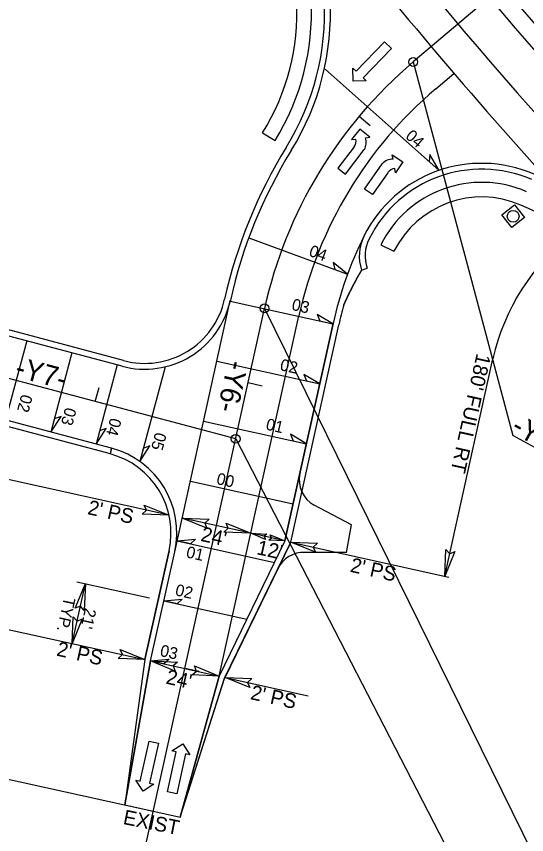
# Model space of a CAD drawing. Extents: x 1762196 to 1766326, y 709922 to 713142.
# Drawn here: x 1763983.5 to 1764158, y 711023.4 to 711303.2 of the extents above; entities that cross this region are included whole.
import ezdxf

# ---------------------------------------------------------------- set-up
doc = ezdxf.new("R2010")
doc.units = 0
for name, color, linetype in [('Default', 7, 'Continuous'), ('Old_Level_3', 7, 'Continuous'), ('Pattern 1', 7, 'Continuous'), ('Pattern 2', 7, 'Continuous'), ('Prop Conc 2ft 6in Curb and Gutter', 7, 'Continuous'), ('Prop Dimension', 7, 'Continuous'), ('Prop EOT', 7, 'Continuous'), ('Prop Horizontal Alignment', 7, 'Continuous'), ('Prop Horizontal Alignment Direction Label', 7, 'Continuous'), ('Prop Horizontal Alignment Station Label', 7, 'Continuous'), ('Prop Horizontal Alignment Tick Small', 7, 'Continuous'), ('Prop Lane Arrow CELL', 7, 'Continuous'), ('Prop Lane Lines', 7, 'Continuous'), ('Prop Paved Shoulder', 7, 'Continuous'), ('Prop Shade Medium', 7, 'Continuous'), ('Prop Superelevation  Arrow CELL', 7, 'Continuous'), ('Prop Superelevation Label', 7, 'Continuous'), ('Prop Terminator CELL', 7, 'Continuous')]:
    doc.layers.add(name, color=color, linetype=linetype)

msp = doc.modelspace()

# ---------------------------------------------------------------- linework, layer by layer
at = {"layer": 'Default'}
msp.add_lwpolyline([(1764157.32, 711234.37), (1764152.96, 711230.97), (1764149.56, 711235.32), (1764153.92, 711238.73)], close=True, dxfattribs=at)
msp.add_circle((1764153.42, 711234.8), 2.03, dxfattribs=at)
at = {"layer": 'Old_Level_3'}
for p, q in [((1764098.14, 711129.25), (1764085.4, 711135.99)), ((1764096.46, 711119.8), (1764098.14, 711129.25)), ((1764096.46, 711119.8), (1764082.2, 711119.9))]:
    msp.add_line(p, q, dxfattribs=at)
for centre, start, end in [((1764090.25, 711144.74), 167.5238, 241.0076), ((1764081.9, 711109.9), 88.294, 154.0891)]:
    msp.add_arc(centre, 10, start, end, dxfattribs=at)
at = {"layer": 'Pattern 1'}
for p, q in [((1764067.74, 711263.33), (1764071.99, 711260.71)), ((1764108.18, 711225.07), (1764112.66, 711222.84))]:
    msp.add_line(p, q, dxfattribs=at)
for centre, radius, start, end in [((1764000.95, 711304.58), 83.5, 328.2999, 36.9925), ((1764000.95, 711304.58), 78.5, 328.2999, 36.9925), ((1764142.65, 711207.92), 38.5, 66.4571, 153.5523), ((1764142.65, 711207.92), 33.5, 66.4571, 153.5523), ((1764088.73, 711084.16), 168.5, 44.7299, 66.4571)]:
    msp.add_arc(centre, radius, start, end, dxfattribs=at)
at = {"layer": 'Pattern 2'}
for p, q in [((1764067.74, 711263.33), (1764071.99, 711260.71)), ((1764108.18, 711225.07), (1764112.66, 711222.84))]:
    msp.add_line(p, q, dxfattribs=at)
for centre, radius, start, end in [((1764000.95, 711304.58), 83.5, 328.2999, 36.9925), ((1764000.95, 711304.58), 78.5, 328.2999, 36.9925), ((1764142.65, 711207.92), 38.5, 66.4571, 153.5523), ((1764142.65, 711207.92), 33.5, 66.4571, 153.5523), ((1764088.73, 711084.16), 168.5, 44.7299, 66.4571)]:
    msp.add_arc(centre, radius, start, end, dxfattribs=at)
at = {"layer": 'Prop Conc 2ft 6in Curb and Gutter'}
for p, q in [((1764101.6, 711216.43), (1764103.49, 711217.08)), ((1764020.2, 711185.46), (1763932.48, 711208.83)), ((1764015.67, 711153.55), (1763924.24, 711177.91)), ((1764015.67, 711153.55), (1764016.1, 711155.51))]:
    msp.add_line(p, q, dxfattribs=at)
for centre, radius, start, end in [((1764000.95, 711304.58), 88, 328.2999, 36.9925), ((1764218.76, 711170.06), 168, 148.2999, 167.4899), ((1764142.65, 711207.92), 43, 66.4571, 153.5523), ((1764115.79, 711221.28), 13, 153.5523, 198.869), ((1764027.41, 711212.52), 28, 255.0839, 347.4899)]:
    msp.add_arc(centre, radius, start, end, dxfattribs=at)
at = {"layer": 'Prop Dimension'}
for p, q in [((1764130.06, 711111.71), (1764146.5, 711186.05)), ((1764035.72, 711132.59), (1763933.52, 711155.2)), ((1764063.66, 711126.4), (1764040.23, 711131.59)), ((1764075.38, 711123.81), (1764063.66, 711126.4)), ((1764077.33, 711123.38), (1764131.45, 711111.4)), ((1763922.72, 711106.38), (1764027.47, 711083.2)), ((1764029.43, 711082.77), (1764052.86, 711077.58)), ((1764054.87, 711077.14), (1764083.34, 711070.84))]:
    msp.add_line(p, q, dxfattribs=at)
msp.add_arc((1764218.76, 711170.06), 74, 127.3856, 167.5238, dxfattribs=at)
at = {"layer": 'Prop EOT'}
for p, q in [((1764019.69, 711183.53), (1763931.97, 711206.9)), ((1764075.38, 711123.81), (1764091.83, 711198.15)), ((1764016.1, 711155.51), (1763924.76, 711179.84)), ((1764075.38, 711123.81), (1764052.86, 711077.58)), ((1764029.43, 711082.77), (1764037.67, 711120.04)), ((1764029.43, 711082.77), (1764020.61, 711033.51)), ((1764039.58, 711029.31), (1764052.86, 711077.58)), ((1764020.61, 711033.51), (1764039.58, 711029.31))]:
    msp.add_line(p, q, dxfattribs=at)
for centre, radius, start, end in [((1764000.95, 711304.58), 90, 328.2999, 36.9925), ((1764218.76, 711170.06), 166, 148.2999, 167.4899), ((1764142.65, 711207.92), 45, 66.4571, 153.5523), ((1764218.76, 711170.06), 130, 153.5523, 167.5238), ((1764027.41, 711212.52), 30, 255.0839, 347.4899), ((1764008.38, 711126.52), 30, 347.5238, 75.0839)]:
    msp.add_arc(centre, radius, start, end, dxfattribs=at)
at = {"layer": 'Prop Horizontal Alignment'}
for p, q in [((1764149.82, 711313.49), (1764119.23, 711287.58)), ((1763997.94, 710884.9), (1764068.39, 711203.33)), ((1764058.52, 711158.7), (1763913.87, 711197.23))]:
    msp.add_line(p, q, dxfattribs=at)
for centre, radius, start, end in [((1765296.46, 712280.56), 1500, 216.32502, 240.8436), ((1764218.76, 711170.06), 154, 130.2612, 167.5238)]:
    msp.add_arc(centre, radius, start, end, dxfattribs=at)
at = {"layer": 'Prop Horizontal Alignment Station Label'}
for p, q in [((1764119.23, 711287.58), (1764153.33, 711159.89)), ((1764068.39, 711203.33), (1764195.76, 710944.38)), ((1764248.6, 711106.84), (1764153.33, 711159.89)), ((1764058.52, 711158.7), (1764174.11, 710934.74)), ((1763823.81, 711077.05), (1764030.34, 711031.36))]:
    msp.add_line(p, q, dxfattribs=at)
for centre in [(1764119.23, 711287.58), (1764068.39, 711203.33), (1764058.52, 711158.7)]:
    msp.add_circle(centre, 1.5, dxfattribs=at)
at = {"layer": 'Prop Horizontal Alignment Tick Small'}
for p, q in [((1764104.55, 711265.75), (1764100.71, 711268.96)), ((1764010.5, 711171.49), (1764011.78, 711176.32)), ((1764067.63, 711176.73), (1764062.75, 711177.81)), ((1764046.03, 711079.1), (1764041.14, 711080.18))]:
    msp.add_line(p, q, dxfattribs=at)
at = {"layer": 'Prop Lane Arrow CELL'}
for p, q in [((1764099.7, 711284.47), (1764109.46, 711294.51)), ((1764109.46, 711294.51), (1764111.82, 711292.22)), ((1764111.82, 711292.22), (1764102.07, 711282.17)), ((1764098.73, 711281.03), (1764098.63, 711285.52)), ((1764098.63, 711285.52), (1764099.7, 711284.47)), ((1764103.15, 711281.13), (1764098.73, 711281.03)), ((1764102.07, 711282.17), (1764103.15, 711281.13)), ((1764100.95, 711264.58), (1764098.18, 711261.04)), ((1764104.42, 711261.88), (1764100.95, 711264.58)), ((1764098.18, 711261.04), (1764099.65, 711261.23)), ((1764102.94, 711261.68), (1764104.42, 711261.88)), ((1764099.05, 711258.55), (1764093.5, 711251.27)), ((1764096.13, 711249.27), (1764102.52, 711257.66)), ((1764112.34, 711254.39), (1764112.08, 711255.85)), ((1764112.08, 711255.85), (1764115.72, 711253.38)), ((1764102.61, 711244.11), (1764108.65, 711252.76)), ((1764115.72, 711253.38), (1764113.19, 711249.66)), ((1764093.5, 711251.27), (1764096.13, 711249.27)), ((1764110.55, 711249.73), (1764105.32, 711242.22)), ((1764113.19, 711249.66), (1764112.93, 711251.12)), ((1764105.32, 711242.22), (1764102.61, 711244.11)), ((1764025.87, 711041.65), (1764028.9, 711055.32)), ((1764028.9, 711055.32), (1764032.12, 711054.6)), ((1764032.12, 711054.6), (1764029.09, 711040.93)), ((1764036.73, 711052.02), (1764040.43, 711054.42)), ((1764040.43, 711054.42), (1764042.88, 711050.66)), ((1764035.16, 711038.03), (1764038.19, 711051.7)), ((1764038.19, 711051.7), (1764036.73, 711052.02)), ((1764041.41, 711050.98), (1764038.38, 711037.31)), ((1764042.88, 711050.66), (1764041.41, 711050.98)), ((1764026.85, 711038.2), (1764024.4, 711041.97)), ((1764024.4, 711041.97), (1764025.87, 711041.65)), ((1764030.55, 711040.61), (1764026.85, 711038.2)), ((1764029.09, 711040.93), (1764030.55, 711040.61)), ((1764038.38, 711037.31), (1764035.16, 711038.03))]:
    msp.add_line(p, q, dxfattribs=at)
for centre, radius, start, end in [((1764096.46, 711260.53), 3.28, 322.6881, 12.3463), ((1764097.93, 711260.17), 5.25, 331.3642, 16.6759), ((1764112.44, 711249.15), 5.25, 91.1316, 136.4433), ((1764113.23, 711247.87), 3.28, 95.4612, 145.1194)]:
    msp.add_arc(centre, radius, start, end, dxfattribs=at)
at = {"layer": 'Prop Lane Lines'}
for p, q in [((1764126.99, 711278.42), (1764133.18, 711283.67)), ((1764037.67, 711120.04), (1764056.69, 711205.99)), ((1764052.86, 711077.58), (1764080.11, 711200.74))]:
    msp.add_line(p, q, dxfattribs=at)
for centre, radius, start, end in [((1765296.46, 712280.56), 1494, 216.32502, 222.11492), ((1765296.46, 712280.56), 1506, 216.32502, 222.11492), ((1765296.46, 712280.56), 1520, 216.32502, 224.72992), ((1765296.46, 712280.56), 1532, 217.53858, 222.47123), ((1764218.76, 711170.06), 142, 130.2612, 167.5238)]:
    msp.add_arc(centre, radius, start, end, dxfattribs=at)
at = {"layer": 'Prop Paved Shoulder'}
for p, q in [((1764077.33, 711123.38), (1764093.78, 711197.71)), ((1764077.33, 711123.38), (1764054.66, 711076.71)), ((1764027.47, 711083.2), (1764035.72, 711120.47)), ((1764027.47, 711083.2), (1764020.61, 711033.51)), ((1764039.58, 711029.31), (1764054.79, 711077.05))]:
    msp.add_line(p, q, dxfattribs=at)
for centre, radius, start, end in [((1764115.79, 711221.28), 15, 153.5523, 198.869), ((1764218.76, 711170.06), 128, 164.3625, 167.5238), ((1764008.38, 711126.52), 28, 347.5238, 75.0839)]:
    msp.add_arc(centre, radius, start, end, dxfattribs=at)
msp.add_spline([(1764101.6, 711216.43), (1764101.46, 711216.19), (1764101.33, 711215.96), (1764101.19, 711215.73), (1764101.06, 711215.49), (1764100.93, 711215.26), (1764100.79, 711215.03), (1764100.66, 711214.79), (1764100.53, 711214.56), (1764100.4, 711214.32), (1764100.27, 711214.09), (1764100.14, 711213.85), (1764100.01, 711213.62), (1764099.88, 711213.38), (1764099.75, 711213.14), (1764099.62, 711212.91), (1764099.49, 711212.67), (1764099.36, 711212.43), (1764099.24, 711212.19), (1764099.11, 711211.96), (1764098.98, 711211.72), (1764098.86, 711211.48), (1764098.73, 711211.24), (1764098.61, 711211), (1764098.48, 711210.76), (1764098.36, 711210.52), (1764098.23, 711210.28), (1764098.11, 711210.04), (1764097.99, 711209.79), (1764097.87, 711209.55), (1764097.75, 711209.31), (1764097.63, 711209.07), (1764097.5, 711208.83), (1764097.38, 711208.58), (1764097.27, 711208.34), (1764097.15, 711208.09), (1764097.03, 711207.85), (1764096.91, 711207.61), (1764096.79, 711207.36), (1764096.67, 711207.12), (1764096.56, 711206.87), (1764096.44, 711206.62), (1764096.33, 711206.38), (1764096.21, 711206.13), (1764096.1, 711205.89), (1764095.98, 711205.64), (1764095.87, 711205.39), (1764095.76, 711205.14), (1764095.64, 711204.89), (1764095.53, 711204.65), (1764095.49, 711204.56)], degree=3, dxfattribs=at)
at = {"layer": 'Prop Shade Medium'}
for p, q in [((1764101.6, 711216.43), (1764101.6, 711216.43)), ((1764101.6, 711216.43), (1764101.6, 711216.43)), ((1764091.83, 711198.15), (1764075.38, 711123.81)), ((1764077.33, 711123.38), (1764093.78, 711197.71)), ((1764016.1, 711155.51), (1764015.59, 711153.57)), ((1764016.1, 711155.51), (1764015.59, 711153.57)), ((1764075.38, 711123.81), (1764052.86, 711077.58)), ((1764054.72, 711076.83), (1764077.33, 711123.38)), ((1764035.72, 711120.47), (1764027.47, 711083.2)), ((1764029.43, 711082.77), (1764037.67, 711120.04)), ((1764027.47, 711083.2), (1764020.61, 711033.51)), ((1764020.61, 711033.51), (1764029.43, 711082.77)), ((1764052.86, 711077.58), (1764039.58, 711029.31)), ((1764039.58, 711029.31), (1764054.72, 711076.83))]:
    msp.add_line(p, q, dxfattribs=at)
for centre, radius, start, end in [((1764218.76, 711170.06), 130, 153.5523, 167.5238), ((1764115.79, 711221.28), 15, 153.5523, 198.869), ((1764218.76, 711170.06), 128, 164.3625, 167.5238), ((1764008.38, 711126.52), 30, 347.5238, 75.0839), ((1764008.38, 711126.52), 28, 347.5238, 75.0839)]:
    msp.add_arc(centre, radius, start, end, dxfattribs=at)
for points in [[(1764098.39, 711210.58), (1764098.48, 711210.76), (1764098.61, 711211), (1764098.73, 711211.24), (1764098.86, 711211.48), (1764098.98, 711211.72), (1764099.11, 711211.96), (1764099.24, 711212.19), (1764099.36, 711212.43), (1764099.49, 711212.67), (1764099.62, 711212.91), (1764099.75, 711213.14), (1764099.88, 711213.38), (1764100.01, 711213.62), (1764100.14, 711213.85), (1764100.27, 711214.09), (1764100.4, 711214.32), (1764100.53, 711214.56), (1764100.66, 711214.79), (1764100.79, 711215.03), (1764100.93, 711215.26), (1764101.06, 711215.49), (1764101.19, 711215.73), (1764101.33, 711215.96), (1764101.46, 711216.19), (1764101.6, 711216.43)], [(1764095.49, 711204.56), (1764095.53, 711204.65), (1764095.64, 711204.89), (1764095.76, 711205.14), (1764095.87, 711205.39), (1764095.98, 711205.64), (1764096.1, 711205.89), (1764096.21, 711206.13), (1764096.33, 711206.38), (1764096.44, 711206.62), (1764096.56, 711206.87), (1764096.67, 711207.12), (1764096.79, 711207.36), (1764096.91, 711207.61), (1764097.03, 711207.85), (1764097.15, 711208.09), (1764097.27, 711208.34), (1764097.38, 711208.58), (1764097.5, 711208.83), (1764097.63, 711209.07), (1764097.75, 711209.31), (1764097.87, 711209.55), (1764097.99, 711209.79), (1764098.11, 711210.04), (1764098.23, 711210.28), (1764098.36, 711210.52), (1764098.39, 711210.58)]]:
    msp.add_spline(points, degree=3, dxfattribs=at)
at = {"layer": 'Prop Superelevation  Arrow CELL'}
for points in [[(1764128.11, 711250.5), (1764124.95, 711255.98), (1764124.65, 711253.57)], [(1764096.78, 711215.03), (1764091.85, 711218.99), (1764092.44, 711216.63)], [(1764091.8, 711198.02), (1764086.37, 711201.26), (1764087.28, 711199.01)], [(1764087.26, 711177.51), (1764081.83, 711180.76), (1764082.74, 711178.51)], [(1763995.3, 711161.05), (1763998.78, 711166.33), (1763996.49, 711165.52)], [(1764010.76, 711156.93), (1764014.24, 711162.21), (1764011.95, 711161.4)], [(1764082.72, 711157.01), (1764077.3, 711160.26), (1764078.21, 711158.01)], [(1764025.73, 711150.99), (1764029.21, 711156.27), (1764026.92, 711155.46)], [(1764038.5, 711123.78), (1764044.79, 711124.43), (1764043.02, 711122.78)], [(1764033.96, 711103.27), (1764040.25, 711103.93), (1764038.48, 711102.27)], [(1764029.43, 711082.77), (1764035.72, 711083.42), (1764033.94, 711081.77)]]:
    msp.add_lwpolyline(points, close=True, dxfattribs=at)
at = {"layer": 'Prop Superelevation Label'}
for p, q in [((1764089.11, 711285.12), (1764128.11, 711250.5)), ((1764063.01, 711227.49), (1764096.78, 711215.03)), ((1764056.65, 711205.79), (1764091.8, 711198.02)), ((1763987.04, 711192.22), (1763979.84, 711165.17)), ((1764002.51, 711188.1), (1763995.3, 711161.05)), ((1764052.11, 711185.29), (1764087.26, 711177.51)), ((1764017.97, 711183.99), (1764010.76, 711156.93)), ((1764034.35, 711183.33), (1764025.73, 711150.99)), ((1764047.57, 711164.78), (1764082.72, 711157.01)), ((1764043.04, 711144.28), (1764078.19, 711136.5)), ((1764038.5, 711123.78), (1764071.78, 711116.41)), ((1764002.59, 711088.71), (1764007.13, 711109.21)), ((1764004.2, 711109.86), (1764029.08, 711104.35)), ((1764033.96, 711103.27), (1764062.32, 711097)), ((1764029.43, 711082.77), (1764052.86, 711077.58))]:
    msp.add_line(p, q, dxfattribs=at)
at = {"layer": 'Prop Terminator CELL'}
for points in [[(1764027.26, 711136.04), (1764035.72, 711132.59), (1764026.53, 711132.98), (1764028, 711134.29)], [(1764048.68, 711128.13), (1764040.23, 711131.59), (1764049.41, 711131.19), (1764047.94, 711129.88)], [(1764055.21, 711129.86), (1764063.66, 711126.4), (1764054.48, 711126.8), (1764055.95, 711128.11)], [(1764068.73, 711124.33), (1764063.66, 711126.4), (1764069.17, 711126.17), (1764068.29, 711125.38)], [(1764070.31, 711125.89), (1764075.38, 711123.81), (1764069.87, 711124.05), (1764070.75, 711124.83)], [(1764085.78, 711119.92), (1764077.33, 711123.38), (1764086.51, 711122.99), (1764085.05, 711121.67)], [(1764133.51, 711120.17), (1764130.06, 711111.71), (1764130.45, 711120.89), (1764131.76, 711119.43)], [(1764003.67, 711100.76), (1764007.13, 711109.21), (1764006.74, 711100.03), (1764005.42, 711101.5)], [(1764006.05, 711097.16), (1764002.59, 711088.71), (1764002.99, 711097.89), (1764004.3, 711096.42)], [(1764019.02, 711086.66), (1764027.47, 711083.2), (1764018.29, 711083.59), (1764019.76, 711084.91)], [(1764037.88, 711079.31), (1764029.43, 711082.77), (1764038.61, 711082.38), (1764037.14, 711081.06)], [(1764044.41, 711081.04), (1764052.86, 711077.58), (1764043.68, 711077.98), (1764045.15, 711079.29)], [(1764063.32, 711073.68), (1764054.87, 711077.14), (1764064.05, 711076.75), (1764062.58, 711075.43)]]:
    msp.add_lwpolyline(points, close=True, dxfattribs=at)

# ---------------------------------------------------------------- texts
at = {"layer": 'Prop Dimension'}
for s, rotation, p in [("180' FULL RT", 257.5238, (1764140.98, 711188.13)), ("2' PS", 347.5238, (1764007.61, 711133)), ("24'", 347.5238, (1764046.31, 711123.84)), ("12'", 347.5238, (1764065.42, 711119.31)), ("2' PS", 347.5238, (1764097.41, 711113.29)), ("2' PS", 347.5238, (1763997.01, 711084.61)), ("24'", 347.5238, (1764034.39, 711075.06)), ("2' PS", 347.5238, (1764063.31, 711069.72)), ('EXIST', 348.605, (1764019.75, 711027.04))]:
    msp.add_text(s, height=5, rotation=rotation, dxfattribs=at).set_placement(p)
at = {"layer": 'Prop Horizontal Alignment Direction Label'}
for s, rotation, p in [('-Y7-', 345.0839, (1763982.71, 711180.09)), ('-Y6- ', 257.5045, (1764056, 711185.9))]:
    msp.add_text(s, height=7, rotation=rotation, dxfattribs=at).set_placement(p)
at = {"layer": 'Prop Horizontal Alignment Station Label'}
msp.add_text('-Y6- PT Sta.  14+26.29', height=7, rotation=330.8875, dxfattribs=at).set_placement((1764152.33, 711161.15))
at = {"layer": 'Prop Superelevation Label'}
for s, rotation, p in [('04', 318.4119, (1764116.29, 711261.83)), ('04', 339.7602, (1764083.27, 711221.39)), ('03', 347.5238, (1764077.43, 711202.84)), ('02', 347.5238, (1764073.44, 711182.23)), ('02', 255.0839, (1763985.26, 711174.16)), ('03', 255.0839, (1764000.27, 711169.68)), ('04', 255.0839, (1764015.68, 711166.1)), ('01', 347.5238, (1764068.61, 711161.88)), ('05', 255.0839, (1764031.08, 711161.18)), ('00', 347.5238, (1764051.72, 711143.29)), ('01', 347.5238, (1764041.35, 711118.2)), ('02', 347.5238, (1764037.61, 711105.23)), ('TYP.', 257.5238, (1763999.86, 711104.81)), ("21'", 257.5238, (1764007.01, 711101.06)), ('03', 347.5238, (1764032.41, 711084.5))]:
    msp.add_text(s, height=4, rotation=rotation, dxfattribs=at).set_placement(p)

doc.saveas('drawing.dxf')
